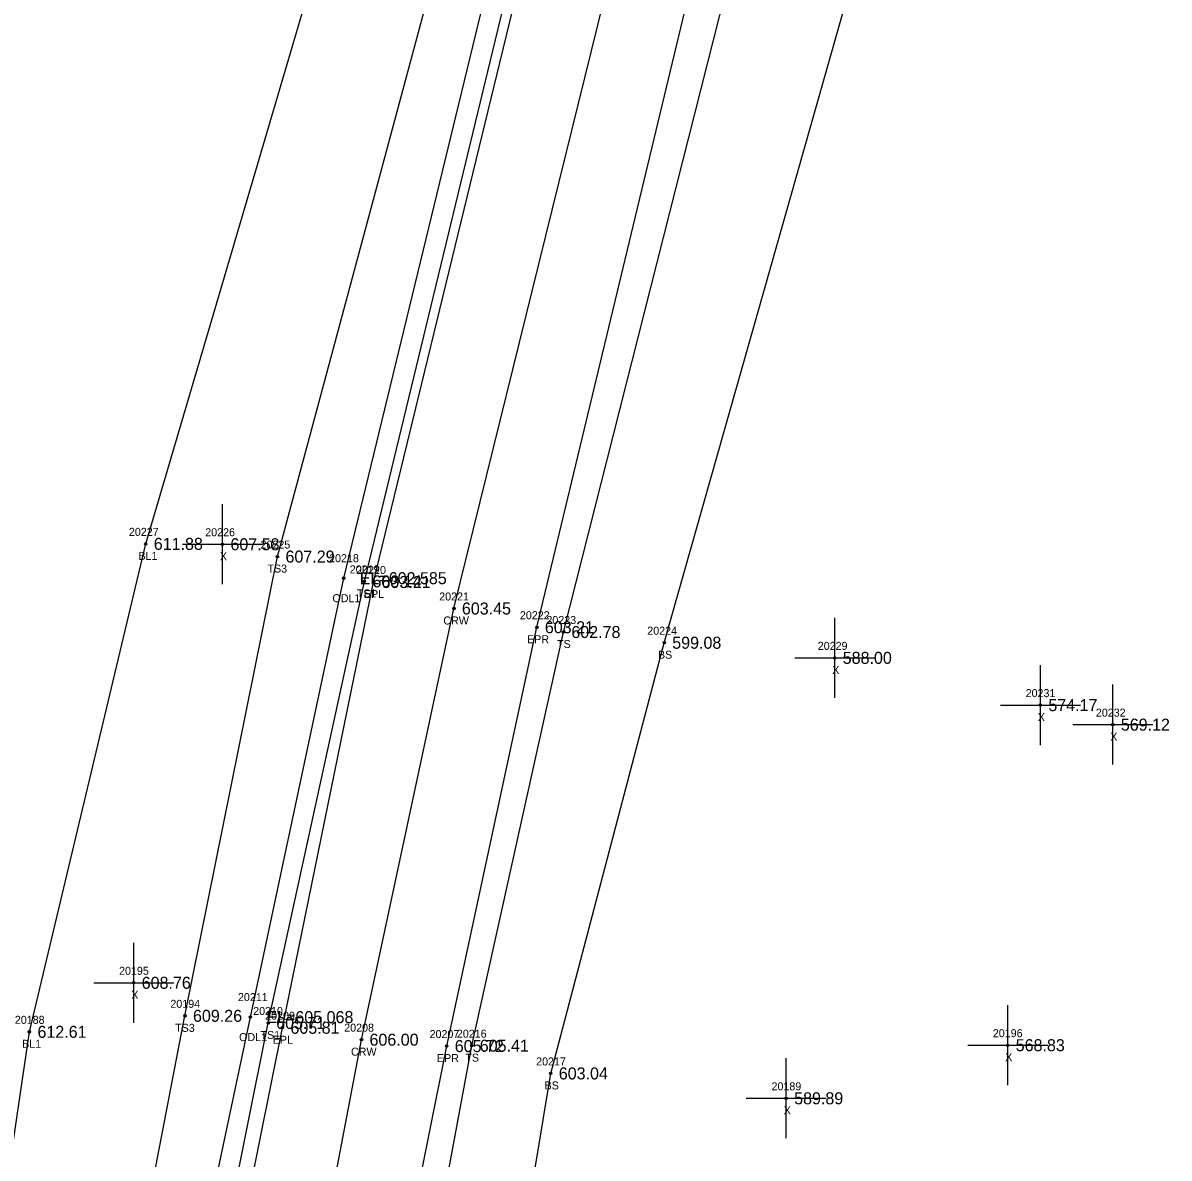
# Model space of a CAD drawing. Extents: x 1695443 to 1696344, y 1087542 to 1090645.
# Drawn here: x 1695929 to 1696072.3, y 1088322.1 to 1088464 of the extents above; entities that cross this region are included whole.
import ezdxf

# ---------------------------------------------------------------- set-up
doc = ezdxf.new("R2010")
doc.units = 0
for name, color, linetype in [('RD_DTM_BkLn1', 7, 'Continuous'), ('RD_DTM_BkLn2', 7, 'Continuous'), ('RD_DTM_BkLn_txCode', 7, 'Continuous'), ('RD_EX_H2O', 7, 'Continuous'), ('RD_EX_H2O_txCode', 7, 'Continuous'), ('RD_EX_Misc', 7, 'Continuous'), ('RD_EX_Misc_txCode', 7, 'Continuous'), ('RD_EX_Road', 7, 'Continuous'), ('RD_EX_Road_txCode', 7, 'Continuous'), ('RD_EX_TX_H2O_ELEV', 7, 'Continuous'), ('RD_EX_TX_Misc_ELEV', 7, 'Continuous'), ('RD_EX_TX_Road_ELEV', 7, 'Continuous'), ('RD_HC_Survey_ELEV', 7, 'Continuous'), ('RD_HC_Survey_txCode', 7, 'Continuous'), ('RD_SMD_Locator', 7, 'Continuous')]:
    doc.layers.add(name, color=color, linetype=linetype)

msp = doc.modelspace()

# ---------------------------------------------------------------- linework, layer by layer
at = {"layer": 'RD_DTM_BkLn1'}
for points in [[(1695869.23, 1087563.38), (1695882.71, 1087666.87), (1695895.39, 1087768.85), (1695908.05, 1087871.3), (1695919.71, 1087974.19), (1695925.35, 1088026.13), (1695931.27, 1088077.73), (1695937.88, 1088128.75), (1695945.4, 1088182.97), (1695952.48, 1088232.38), (1695961.74, 1088286.36), (1695971.36, 1088336.92), (1695982.91, 1088390.82), (1696009.16, 1088497.22), (1696035.45, 1088601.7), (1696045.5, 1088655.66), (1696049.03, 1088705.78), (1696045.47, 1088756.42), (1696033.82, 1088809.1), (1696016.78, 1088855.71), (1695990.89, 1088906.17), (1695964.41, 1088947.39), (1695931.21, 1088992.88)], [(1695919.84, 1088133.52), (1695913.76, 1088189.35), (1695918.21, 1088235.47), (1695922.76, 1088289.81), (1695929.86, 1088337.9), (1695944.4, 1088398.9), (1695974.86, 1088502.33), (1696013.19, 1088605.35)]]:
    msp.add_lwpolyline(points, dxfattribs=at)
at = {"layer": 'RD_DTM_BkLn2'}
for points in [[(1695957.06, 1088113.83), (1695958.4, 1088124.86), (1695969.72, 1088175.5), (1695984.45, 1088233.12), (1695986.34, 1088280.33), (1695995.02, 1088332.7), (1696009.2, 1088386.54), (1696038.3, 1088489.24), (1696061.78, 1088594.39), (1696062.98, 1088655.37), (1696069.05, 1088704.28), (1696065.26, 1088759.68), (1696052.53, 1088814.08), (1696046.96, 1088869.93), (1696016.66, 1088919.05), (1695997.75, 1088967.45), (1695944.59, 1089014.67), (1695937.23, 1089009.08)], [(1695916.78, 1088084), (1695925.73, 1088132.37), (1695932.55, 1088186.85), (1695940.12, 1088233.39), (1695949.48, 1088288.14), (1695959.7, 1088339.01), (1695971.73, 1088394.21), (1695997.36, 1088500.21), (1696023.08, 1088603.25), (1696032.92, 1088656.94), (1696036.1, 1088705.18), (1696032.76, 1088754.54), (1696021.34, 1088805.78), (1696004.42, 1088850.43), (1695979.2, 1088899.43), (1695947.85, 1088934.07), (1695935.29, 1088941.42), (1695930.1, 1088962.13), (1695923.44, 1088976.06), (1695917.46, 1088980.5), (1695920.03, 1088983.92)], [(1695811.33, 1088056.44), (1695848.8, 1088075.62), (1695896.28, 1088098.14), (1695916.78, 1088084), (1695919.84, 1088133.52), (1695923.64, 1088187.73), (1695930.8, 1088232.96), (1695939.58, 1088289.44), (1695949.3, 1088339.9), (1695960.86, 1088397.31), (1695988.69, 1088500.86), (1696013.19, 1088605.35), (1696020.87, 1088659.75), (1696023.4, 1088706.14), (1696018.3, 1088755.38), (1696009.58, 1088802.31), (1695993.24, 1088846.7), (1695969.88, 1088894.03), (1695962.8, 1088910.68)], [(1695882.6, 1087560.4), (1695895.55, 1087664.54), (1695908.06, 1087766.74), (1695920.67, 1087869.68), (1695933.47, 1087972.17), (1695938.06, 1088020.68), (1695943.39, 1088076.15), (1695950.93, 1088126.12), (1695958.62, 1088180.79), (1695967.59, 1088232.03), (1695975.32, 1088283.22), (1695985.14, 1088336.17), (1695996.59, 1088387.88), (1696023.18, 1088492.82), (1696049.23, 1088599.85), (1696058.32, 1088654.25)]]:
    msp.add_lwpolyline(points, dxfattribs=at)
at = {"layer": 'RD_EX_H2O'}
msp.add_lwpolyline([(1695916.78, 1088084), (1695923.72, 1088132.78), (1695929.91, 1088186.51), (1695936.75, 1088234.45), (1695946.8, 1088289.18), (1695957.47, 1088339.74), (1695969.14, 1088394.61), (1695994.85, 1088500.6), (1696021.07, 1088603.21), (1696031.1, 1088657.25), (1696033.92, 1088705.19), (1696029.81, 1088754.45), (1696018.23, 1088805.15), (1696001.4, 1088849.48), (1695973.58, 1088895.84), (1695962.8, 1088910.68)], dxfattribs=at)
at = {"layer": 'RD_EX_Misc'}
for p, q in [((1695953.98, 1088393.85), (1695953.98, 1088403.85)), ((1695948.98, 1088398.85), (1695958.98, 1088398.85)), ((1696030.51, 1088379.65), (1696030.51, 1088389.65)), ((1696025.51, 1088384.65), (1696035.51, 1088384.65)), ((1696056.21, 1088373.74), (1696056.21, 1088383.74)), ((1696065.27, 1088371.3), (1696065.27, 1088381.3)), ((1696051.21, 1088378.74), (1696061.21, 1088378.74)), ((1696060.27, 1088376.3), (1696070.27, 1088376.3)), ((1695942.89, 1088339.03), (1695942.89, 1088349.03)), ((1695937.89, 1088344.03), (1695947.89, 1088344.03)), ((1696052.13, 1088331.23), (1696052.13, 1088341.23)), ((1696047.13, 1088336.23), (1696057.13, 1088336.23)), ((1696024.44, 1088324.59), (1696024.44, 1088334.59)), ((1696019.44, 1088329.59), (1696029.44, 1088329.59))]:
    msp.add_line(p, q, dxfattribs=at)
at = {"layer": 'RD_EX_Road'}
for points in [[(1695879.87, 1087561.29), (1695893.33, 1087665.71), (1695905.96, 1087767.16), (1695918.66, 1087869.54), (1695930.87, 1087972.82), (1695936.26, 1088023.68), (1695942.14, 1088076.32), (1695948.07, 1088128.17), (1695955.04, 1088181.4), (1695962.88, 1088230.72), (1695971.68, 1088284.64), (1695982.02, 1088336.12), (1695993.28, 1088388.48), (1696018.75, 1088494.48), (1696045.23, 1088599.95), (1696055.72, 1088654.41), (1696060.15, 1088705.35), (1696055.83, 1088758.02), (1696044.01, 1088812.16), (1696026.4, 1088860.33), (1696000.41, 1088911.48), (1695972.46, 1088953.82), (1695939.48, 1088998.73), (1695931.21, 1088992.88)], [(1695858.19, 1087564.9), (1695871.71, 1087668.82), (1695884.5, 1087774.69), (1695887.48, 1087794.2), (1695897.57, 1087873.43), (1695908.92, 1087975.76), (1695914.49, 1088029.24), (1695917.65, 1088054.8), (1695920.27, 1088079.09), (1695926.98, 1088130.26), (1695934.75, 1088185.09), (1695942.15, 1088234.62), (1695951.36, 1088288.06), (1695961.48, 1088338.41), (1695972.86, 1088394.13), (1695998.53, 1088499.67), (1696024.81, 1088603.86), (1696034.83, 1088656.78)]]:
    msp.add_lwpolyline(points, dxfattribs=at)
at = {"layer": 'RD_SMD_Locator'}
for centre in [(1695944.4, 1088398.9), (1695953.98, 1088398.85), (1695960.86, 1088397.31), (1695969.14, 1088394.61), (1695971.73, 1088394.21), (1695972.86, 1088394.13), (1695982.91, 1088390.82), (1695993.28, 1088388.48), (1695996.59, 1088387.88), (1696009.2, 1088386.54), (1696030.51, 1088384.65), (1696056.21, 1088378.74), (1696065.27, 1088376.3), (1695942.89, 1088344.03), (1695949.3, 1088339.9), (1695957.47, 1088339.74), (1695959.7, 1088339.01), (1695961.48, 1088338.41), (1695929.86, 1088337.9), (1695971.36, 1088336.92), (1695982.02, 1088336.12), (1695985.14, 1088336.17), (1696052.13, 1088336.23), (1695995.02, 1088332.7), (1696024.44, 1088329.59)]:
    msp.add_circle(centre, 0.15, dxfattribs=at)

# ---------------------------------------------------------------- texts
at = {"layer": 'RD_DTM_BkLn_txCode'}
for s, p in [('20227', (1695942.29, 1088399.9)), ('20225', (1695958.74, 1088398.31)), ('BL1', (1695943.48, 1088396.9)), ('TS3', (1695959.61, 1088395.31)), ('20219', (1695969.89, 1088395.21)), ('TS1', (1695970.77, 1088392.21)), ('20223', (1695994.47, 1088388.88)), ('20224', (1696007.08, 1088387.54)), ('TS', (1695995.8, 1088385.88)), ('BS', (1696008.42, 1088384.54)), ('20194', (1695947.47, 1088340.9)), ('20188', (1695928.03, 1088338.9)), ('20210', (1695957.82, 1088340.01)), ('TS3', (1695948.06, 1088337.9)), ('TS1', (1695958.74, 1088337.01)), ('20216', (1695983.28, 1088337.17)), ('BL1', (1695928.94, 1088335.9)), ('TS', (1695984.34, 1088334.17)), ('20217', (1695993.19, 1088333.7)), ('BS', (1695994.24, 1088330.7))]:
    msp.add_text(s, height=1, dxfattribs=at).set_placement(p)
at = {"layer": 'RD_EX_H2O_txCode'}
for s, p in [('20218', (1695967.31, 1088396.61)), ('ODL1', (1695967.73, 1088391.61)), ('20211', (1695955.92, 1088341.74)), ('ODL1', (1695956.06, 1088336.74))]:
    msp.add_text(s, height=1, dxfattribs=at).set_placement(p)
at = {"layer": 'RD_EX_Misc_txCode'}
for s, p in [('20226', (1695951.83, 1088399.85)), ('X', (1695953.66, 1088396.85)), ('20229', (1696028.39, 1088385.65)), ('X', (1696030.19, 1088382.65)), ('20231', (1696054.37, 1088379.74)), ('X', (1696055.89, 1088376.74)), ('20232', (1696063.15, 1088377.3)), ('X', (1696064.95, 1088374.3)), ('20195', (1695941.06, 1088345.03)), ('X', (1695942.58, 1088342.03)), ('20196', (1696050.27, 1088337.23)), ('X', (1696051.82, 1088334.23)), ('20189', (1696022.61, 1088330.59)), ('X', (1696024.13, 1088327.59))]:
    msp.add_text(s, height=1, dxfattribs=at).set_placement(p)
at = {"layer": 'RD_EX_Road_txCode'}
for s, p in [('20220', (1695970.7, 1088395.13)), ('EPL', (1695971.66, 1088392.13)), ('20222', (1695991.16, 1088389.48)), ('EPR', (1695992.05, 1088386.48)), ('20209', (1695959.32, 1088339.41)), ('EPL', (1695960.27, 1088336.41)), ('20207', (1695979.87, 1088337.12)), ('EPR', (1695980.79, 1088334.12))]:
    msp.add_text(s, height=1, dxfattribs=at).set_placement(p)
at = {"layer": 'RD_EX_TX_H2O_ELEV'}
for s, p in [('EL=602.585', (1695971.14, 1088393.86)), ('EL=605.068', (1695959.47, 1088338.99))]:
    msp.add_text(s, height=1.5, dxfattribs=at).set_placement(p)
at = {"layer": 'RD_EX_TX_Misc_ELEV'}
for s, p in [('611.88', (1695945.4, 1088398.15)), ('607.58', (1695954.98, 1088398.1)), ('607.29', (1695961.86, 1088396.56)), ('603.14', (1695972.73, 1088393.46)), ('602.78', (1695997.59, 1088387.13)), ('599.08', (1696010.2, 1088385.79)), ('588.00', (1696031.51, 1088383.9)), ('574.17', (1696057.21, 1088377.99)), ('569.12', (1696066.27, 1088375.55)), ('608.76', (1695943.89, 1088343.28)), ('609.26', (1695950.3, 1088339.15)), ('612.61', (1695930.86, 1088337.15)), ('605.71', (1695960.7, 1088338.26)), ('568.83', (1696053.13, 1088335.48)), ('605.41', (1695986.14, 1088335.42)), ('603.04', (1695996.02, 1088331.95)), ('589.89', (1696025.44, 1088328.84))]:
    msp.add_text(s, height=1.5, dxfattribs=at).set_placement(p)
at = {"layer": 'RD_EX_TX_Road_ELEV'}
for s, p in [('603.21', (1695973.86, 1088393.38)), ('603.21', (1695994.28, 1088387.73)), ('605.81', (1695962.48, 1088337.66)), ('605.72', (1695983.02, 1088335.37))]:
    msp.add_text(s, height=1.5, dxfattribs=at).set_placement(p)
at = {"layer": 'RD_HC_Survey_ELEV'}
for s, p in [('603.45', (1695983.91, 1088390.07)), ('606.00', (1695972.36, 1088336.17))]:
    msp.add_text(s, height=1.5, dxfattribs=at).set_placement(p)
at = {"layer": 'RD_HC_Survey_txCode'}
for s, p in [('20221', (1695981.07, 1088391.82)), ('CRW', (1695981.59, 1088388.82)), ('20208', (1695969.2, 1088337.92)), ('CRW', (1695970.05, 1088334.92))]:
    msp.add_text(s, height=1, dxfattribs=at).set_placement(p)

doc.saveas('drawing.dxf')
